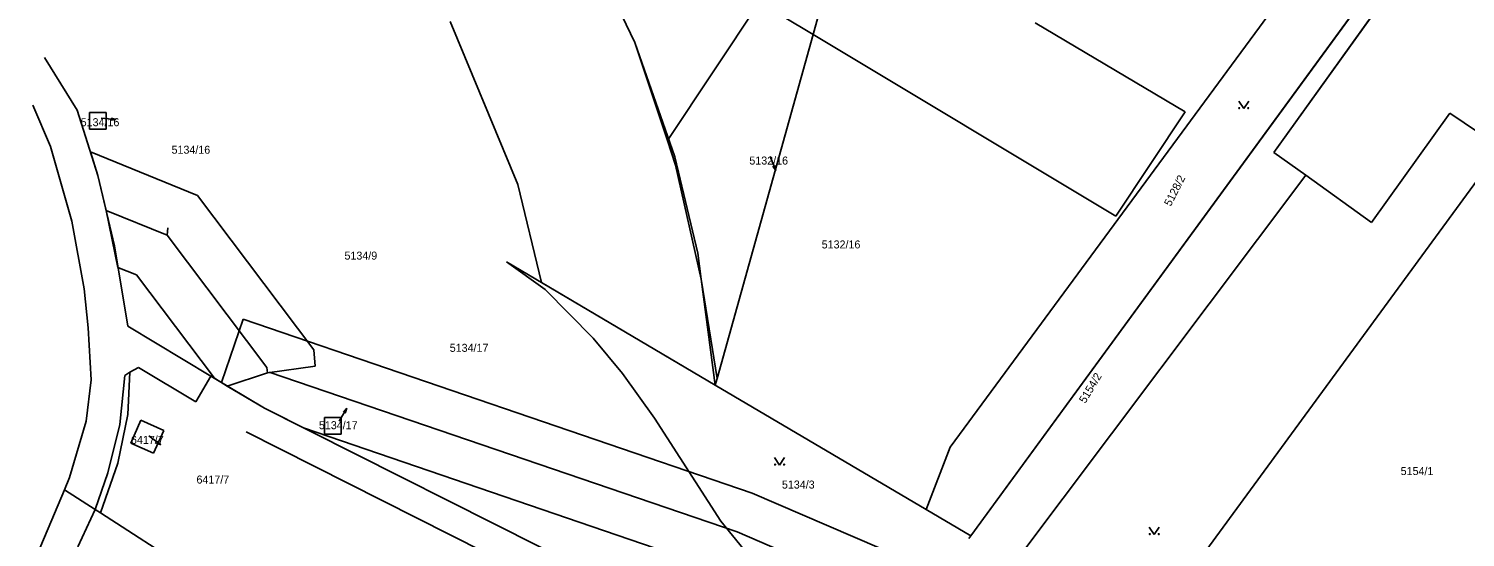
# Model space of a CAD drawing. Extents: x -400488 to -400124, y -1251493 to -1251223.
# Drawn here: x -400488 to -400401.8, y -1251435.6 to -1251405.1 of the extents above; entities that cross this region are included whole.
import ezdxf

# ---------------------------------------------------------------- set-up
doc = ezdxf.new("R2010")
doc.units = 0
doc.layers.add('Level 63', color=7, linetype='Continuous')

msp = doc.modelspace()

# ---------------------------------------------------------------- linework, layer by layer
at = {"layer": 'Level 63'}
for p, q in [((-400486.61, -1251378.03), (-400440.9, -1251405.43)), ((-400432.67, -1251430.17), (-400399.19, -1251384.72)), ((-400399.19, -1251384.72), (-400432.67, -1251430.17)), ((-400395.83, -1251386.77), (-400431.43, -1251435.5)), ((-400431.43, -1251435.5), (-400395.83, -1251386.77)), ((-400413.25, -1251412.5), (-400399.26, -1251392.99)), ((-400399.26, -1251392.99), (-400413.25, -1251412.5)), ((-400438.77, -1251397.77), (-400440.9, -1251405.43)), ((-400440.9, -1251405.43), (-400438.77, -1251397.77)), ((-400455.12, -1251398.59), (-400451.59, -1251405.9)), ((-400455.12, -1251398.59), (-400451.59, -1251405.9)), ((-400444.11, -1251403.5), (-400449.63, -1251411.78)), ((-400449.63, -1251411.78), (-400444.11, -1251403.5)), ((-400458.62, -1251414.42), (-400462.68, -1251404.65)), ((-400458.62, -1251414.42), (-400462.68, -1251404.65)), ((-400440.9, -1251405.43), (-400446.66, -1251426.06)), ((-400446.66, -1251426.06), (-400440.9, -1251405.43)), ((-400440.9, -1251405.43), (-400422.73, -1251416.32)), ((-400440.9, -1251405.43), (-400422.73, -1251416.32)), ((-400418.57, -1251410.06), (-400427.58, -1251404.74)), ((-400418.57, -1251410.06), (-400427.58, -1251404.74)), ((-400451.59, -1251405.9), (-400449.19, -1251412.76)), ((-400451.59, -1251405.9), (-400449.63, -1251411.78)), ((-400487.02, -1251406.81), (-400485.05, -1251409.96)), ((-400486.65, -1251412.15), (-400487.71, -1251409.66)), ((-400415.36, -1251409.42), (-400415.06, -1251409.87)), ((-400415.06, -1251409.87), (-400414.76, -1251409.42)), ((-400483.81, -1251413.88), (-400485.05, -1251409.96)), ((-400485.05, -1251409.96), (-400483.81, -1251413.88)), ((-400484.31, -1251410.11), (-400484.31, -1251411.11)), ((-400483.31, -1251410.11), (-400484.31, -1251410.11)), ((-400484.31, -1251411.11), (-400484.31, -1251410.11)), ((-400484.31, -1251410.11), (-400483.31, -1251410.11)), ((-400483.61, -1251410.45), (-400482.714, -1251410.532)), ((-400483.31, -1251411.11), (-400483.31, -1251410.11)), ((-400483.31, -1251410.11), (-400483.31, -1251411.11)), ((-400483.018, -1251410.564), (-400482.714, -1251410.532)), ((-400482.714, -1251410.532), (-400483.007, -1251410.445)), ((-400422.73, -1251416.32), (-400418.57, -1251410.06)), ((-400422.73, -1251416.32), (-400418.57, -1251410.06)), ((-400402.69, -1251410.14), (-400407.39, -1251416.7)), ((-400407.39, -1251416.7), (-400402.69, -1251410.14)), ((-400400.98, -1251411.3), (-400402.69, -1251410.14)), ((-400402.69, -1251410.14), (-400400.98, -1251411.3)), ((-400484.31, -1251411.11), (-400483.31, -1251411.11)), ((-400483.31, -1251411.11), (-400484.31, -1251411.11)), ((-400398.73, -1251410.99), (-400425.47, -1251447.5)), ((-400485.38, -1251416.62), (-400486.65, -1251412.15)), ((-400449.63, -1251411.78), (-400449.15, -1251413.26)), ((-400449.15, -1251413.26), (-400449.63, -1251411.78)), ((-400449.63, -1251411.78), (-400449.15, -1251413.26)), ((-400484.26, -1251412.47), (-400477.83, -1251415.09)), ((-400483.81, -1251413.88), (-400484.26, -1251412.47)), ((-400484.26, -1251412.47), (-400483.81, -1251413.88)), ((-400449.19, -1251412.76), (-400447.81, -1251418.55)), ((-400449.15, -1251413.26), (-400447.61, -1251420.1)), ((-400447.61, -1251420.1), (-400449.15, -1251413.26)), ((-400449.15, -1251413.26), (-400447.61, -1251420.1)), ((-400443.47, -1251412.75), (-400443.143, -1251413.589)), ((-400443.143, -1251413.589), (-400443.196, -1251413.287)), ((-400411.33, -1251413.87), (-400413.25, -1251412.5)), ((-400413.25, -1251412.5), (-400411.33, -1251413.87)), ((-400482.82, -1251418.11), (-400483.81, -1251413.88)), ((-400483.32, -1251415.98), (-400483.81, -1251413.88)), ((-400483.81, -1251413.88), (-400482.82, -1251418.11)), ((-400483.81, -1251413.88), (-400482.82, -1251418.11)), ((-400443.308, -1251413.331), (-400443.143, -1251413.589)), ((-400411.33, -1251413.87), (-400428.79, -1251437.09)), ((-400428.79, -1251437.09), (-400411.33, -1251413.87)), ((-400407.39, -1251416.7), (-400411.33, -1251413.87)), ((-400411.33, -1251413.87), (-400407.39, -1251416.7)), ((-400457.19, -1251420.31), (-400458.62, -1251414.42)), ((-400457.19, -1251420.31), (-400458.62, -1251414.42)), ((-400477.83, -1251415.09), (-400470.86, -1251424.34)), ((-400484.63, -1251420.69), (-400485.38, -1251416.62)), ((-400482.61, -1251419.4), (-400483.32, -1251415.98)), ((-400483.32, -1251415.98), (-400479.66, -1251417.47)), ((-400479.66, -1251417.47), (-400479.61, -1251417.02)), ((-400479.66, -1251417.47), (-400473.68, -1251425.4)), ((-400482.02, -1251422.93), (-400482.82, -1251418.11)), ((-400482.82, -1251418.11), (-400482.61, -1251419.4)), ((-400482.82, -1251418.11), (-400482.02, -1251422.93)), ((-400456.97, -1251420.73), (-400459.3, -1251419.06)), ((-400459.3, -1251419.06), (-400446.77, -1251426.45)), ((-400459.3, -1251419.06), (-400456.97, -1251420.73)), ((-400446.77, -1251426.45), (-400459.3, -1251419.06)), ((-400447.81, -1251418.55), (-400447.61, -1251420.1)), ((-400481.49, -1251419.85), (-400482.61, -1251419.4)), ((-400476.82, -1251426.04), (-400481.49, -1251419.85)), ((-400447.61, -1251420.1), (-400446.66, -1251426.06)), ((-400446.66, -1251426.06), (-400447.61, -1251420.1)), ((-400447.61, -1251420.1), (-400446.77, -1251426.45)), ((-400447.61, -1251420.1), (-400446.77, -1251426.45)), ((-400484.4, -1251423.03), (-400484.63, -1251420.69)), ((-400446.77, -1251426.45), (-400457.19, -1251420.31)), ((-400446.77, -1251426.45), (-400457.19, -1251420.31)), ((-400454.09, -1251423.64), (-400456.97, -1251420.73)), ((-400456.97, -1251420.73), (-400454.09, -1251423.64)), ((-400476.39, -1251426.3), (-400475.1, -1251422.5)), ((-400475.1, -1251422.5), (-400444.55, -1251432.93)), ((-400484.22, -1251426.14), (-400484.4, -1251423.03)), ((-400477.03, -1251425.92), (-400482.02, -1251422.93)), ((-400482.02, -1251422.93), (-400477.03, -1251425.92)), ((-400470.86, -1251424.34), (-400470.77, -1251425.32)), ((-400452.33, -1251425.76), (-400454.09, -1251423.64)), ((-400454.09, -1251423.64), (-400452.33, -1251425.76)), ((-400470.77, -1251425.32), (-400473.64, -1251425.71)), ((-400484.51, -1251428.62), (-400484.22, -1251426.14)), ((-400482.2, -1251425.88), (-400482.49, -1251428.81)), ((-400481.89, -1251425.67), (-400482.2, -1251425.88)), ((-400482.02, -1251428.21), (-400481.89, -1251425.67)), ((-400481.89, -1251425.67), (-400482.02, -1251428.21)), ((-400481.89, -1251425.67), (-400481.37, -1251425.4)), ((-400481.37, -1251425.4), (-400481.89, -1251425.67)), ((-400481.37, -1251425.4), (-400477.94, -1251427.45)), ((-400477.94, -1251427.45), (-400481.37, -1251425.4)), ((-400477.94, -1251427.45), (-400477.03, -1251425.92)), ((-400477.03, -1251425.92), (-400477.94, -1251427.45)), ((-400473.82, -1251427.84), (-400477.03, -1251425.92)), ((-400477.03, -1251425.92), (-400473.82, -1251427.84)), ((-400476.05, -1251426.51), (-400476.82, -1251426.04)), ((-400473.64, -1251425.71), (-400476.05, -1251426.51)), ((-400473.68, -1251425.4), (-400473.64, -1251425.71)), ((-400473.54, -1251425.67), (-400445.45, -1251435.26)), ((-400450.42, -1251428.43), (-400452.33, -1251425.76)), ((-400452.33, -1251425.76), (-400450.42, -1251428.43)), ((-400446.66, -1251426.06), (-400446.77, -1251426.45)), ((-400446.77, -1251426.45), (-400446.66, -1251426.06)), ((-400476.05, -1251426.51), (-400476.39, -1251426.3)), ((-400473.82, -1251427.84), (-400476.05, -1251426.51)), ((-400446.77, -1251426.45), (-400434.11, -1251433.92)), ((-400434.11, -1251433.92), (-400446.77, -1251426.45)), ((-400438.81, -1251445.43), (-400473.82, -1251427.84)), ((-400473.82, -1251427.84), (-400438.81, -1251445.43)), ((-400471.48, -1251429.02), (-400473.82, -1251427.84)), ((-400469.33, -1251428.62), (-400468.88, -1251427.84)), ((-400468.88, -1251427.84), (-400469.082, -1251428.07)), ((-400468.978, -1251428.13), (-400468.88, -1251427.84)), ((-400485.51, -1251432), (-400484.51, -1251428.62)), ((-400482.61, -1251431.13), (-400482.02, -1251428.21)), ((-400482.02, -1251428.21), (-400482.61, -1251431.13)), ((-400481.23, -1251428.56), (-400481.84, -1251429.93)), ((-400481.84, -1251429.93), (-400481.23, -1251428.56)), ((-400479.86, -1251429.17), (-400481.23, -1251428.56)), ((-400481.23, -1251428.56), (-400479.86, -1251429.17)), ((-400470.22, -1251428.4), (-400470.22, -1251429.4)), ((-400469.22, -1251428.4), (-400470.22, -1251428.4)), ((-400470.22, -1251429.4), (-400470.22, -1251428.4)), ((-400470.22, -1251428.4), (-400469.22, -1251428.4)), ((-400469.22, -1251429.4), (-400469.22, -1251428.4)), ((-400469.22, -1251428.4), (-400469.22, -1251429.4)), ((-400446.43, -1251434.61), (-400450.42, -1251428.43)), ((-400450.42, -1251428.43), (-400446.43, -1251434.61)), ((-400482.49, -1251428.81), (-400483.22, -1251431.71)), ((-400480.75, -1251429.5), (-400480.029, -1251430.039)), ((-400480.47, -1251430.54), (-400479.86, -1251429.17)), ((-400479.86, -1251429.17), (-400480.47, -1251430.54)), ((-400474.92, -1251429.25), (-400431.38, -1251451.21)), ((-400446.35, -1251437.6), (-400471.48, -1251429.02)), ((-400470.22, -1251429.4), (-400469.22, -1251429.4)), ((-400469.22, -1251429.4), (-400470.22, -1251429.4)), ((-400481.84, -1251429.93), (-400480.47, -1251430.54)), ((-400480.47, -1251430.54), (-400481.84, -1251429.93)), ((-400480.306, -1251429.908), (-400480.029, -1251430.039)), ((-400480.029, -1251430.039), (-400480.234, -1251429.811)), ((-400434.11, -1251433.92), (-400432.67, -1251430.17)), ((-400432.67, -1251430.17), (-400434.11, -1251433.92)), ((-400483.65, -1251434.12), (-400482.61, -1251431.13)), ((-400482.61, -1251431.13), (-400483.65, -1251434.12)), ((-400443.21, -1251430.8), (-400442.91, -1251431.25)), ((-400442.91, -1251431.25), (-400442.61, -1251430.8)), ((-400485.82, -1251432.73), (-400485.51, -1251432)), ((-400483.22, -1251431.71), (-400483.98, -1251433.91)), ((-400487.96, -1251437.79), (-400485.82, -1251432.73)), ((-400483.98, -1251433.91), (-400485.82, -1251432.73)), ((-400485.82, -1251432.73), (-400483.98, -1251433.91)), ((-400444.55, -1251432.93), (-400433.16, -1251437.83)), ((-400483.98, -1251433.91), (-400485.01, -1251436.16)), ((-400483.65, -1251434.12), (-400483.98, -1251433.91)), ((-400483.98, -1251433.91), (-400483.65, -1251434.12)), ((-400431.43, -1251435.5), (-400434.11, -1251433.92)), ((-400434.11, -1251433.92), (-400431.43, -1251435.5)), ((-400477.32, -1251438.19), (-400483.65, -1251434.12)), ((-400483.65, -1251434.12), (-400477.32, -1251438.19)), ((-400443.8, -1251437.85), (-400446.43, -1251434.61)), ((-400446.43, -1251434.61), (-400443.8, -1251437.85)), ((-400445.45, -1251435.26), (-400434.69, -1251439.89)), ((-400431.55, -1251435.66), (-400431.43, -1251435.5)), ((-400431.43, -1251435.5), (-400431.55, -1251435.66)), ((-400420.73, -1251434.97), (-400420.43, -1251435.42)), ((-400420.43, -1251435.42), (-400420.13, -1251434.97))]:
    msp.add_line(p, q, dxfattribs=at)
for centre in [(-400415.33, -1251409.84), (-400414.79, -1251409.84), (-400443.18, -1251431.22), (-400442.64, -1251431.22), (-400420.7, -1251435.39), (-400420.16, -1251435.39)]:
    msp.add_circle(centre, 0.03, dxfattribs=at)

# ---------------------------------------------------------------- texts
for s, p in [('5134/16', (-400484.842, -1251410.93)), ('5134/16', (-400479.392, -1251412.58)), ('5132/16', (-400444.723, -1251413.23)), ('5134/9', (-400469.016, -1251418.93)), ('5132/16', (-400440.383, -1251418.26)), ('5134/17', (-400462.7, -1251424.46)), ('5134/17', (-400470.55, -1251429.1)), ('6417/7', (-400481.825, -1251429.98)), ('5154/1', (-400405.646, -1251431.85)), ('6417/7', (-400477.895, -1251432.36)), ('5134/3', (-400442.77, -1251432.66))]:
    msp.add_text(s, height=0.48, dxfattribs=at).set_placement(p)
for s, rotation, p in [('5128/2', 62.83, (-400419.443, -1251415.771)), ('5154/2', 58.95, (-400424.569, -1251427.589))]:
    msp.add_text(s, height=0.48, rotation=rotation, dxfattribs=at).set_placement(p)

doc.saveas('drawing.dxf')
